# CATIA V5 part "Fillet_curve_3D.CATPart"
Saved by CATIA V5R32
Part number: Part1
Bounding box of the stored display mesh (mm): x -53.144 to 62.813, y -26.849 to 28.582, z -46.959 to 56.805
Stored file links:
  D:\PROJECTS\Project 2022\CATIA V5 6R 2022\Resources\Part Files\c17_catia_v6_6r2022_prt\Fillet_curve_3D.CATPart
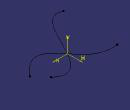
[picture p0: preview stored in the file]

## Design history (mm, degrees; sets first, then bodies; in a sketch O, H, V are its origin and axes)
Body1 (main body)
  Sketch1 on xy-plane, origin (0, 0, 0), H (1, 0, 0), V (0, 1, 0)
    spline S1 through (-53.144, 27.9693) (-18.6897, 19.5729) (20.5127, -19.6499) (62.8125, 1.293)
    coincidence: O S1
  Sketch2 on yz-plane, origin (0, 0, 0), H (0, 1, 0), V (0, 0, 1)
    spline S1 through (-6.7941, 56.8054) (-23.6522, 28.3211) (0, 0) (-26.8494, -46.959)
    point P1 (0, 0)
    coincidence: P1 H, P1 O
